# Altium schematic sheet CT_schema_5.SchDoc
size 255 x 245 mm
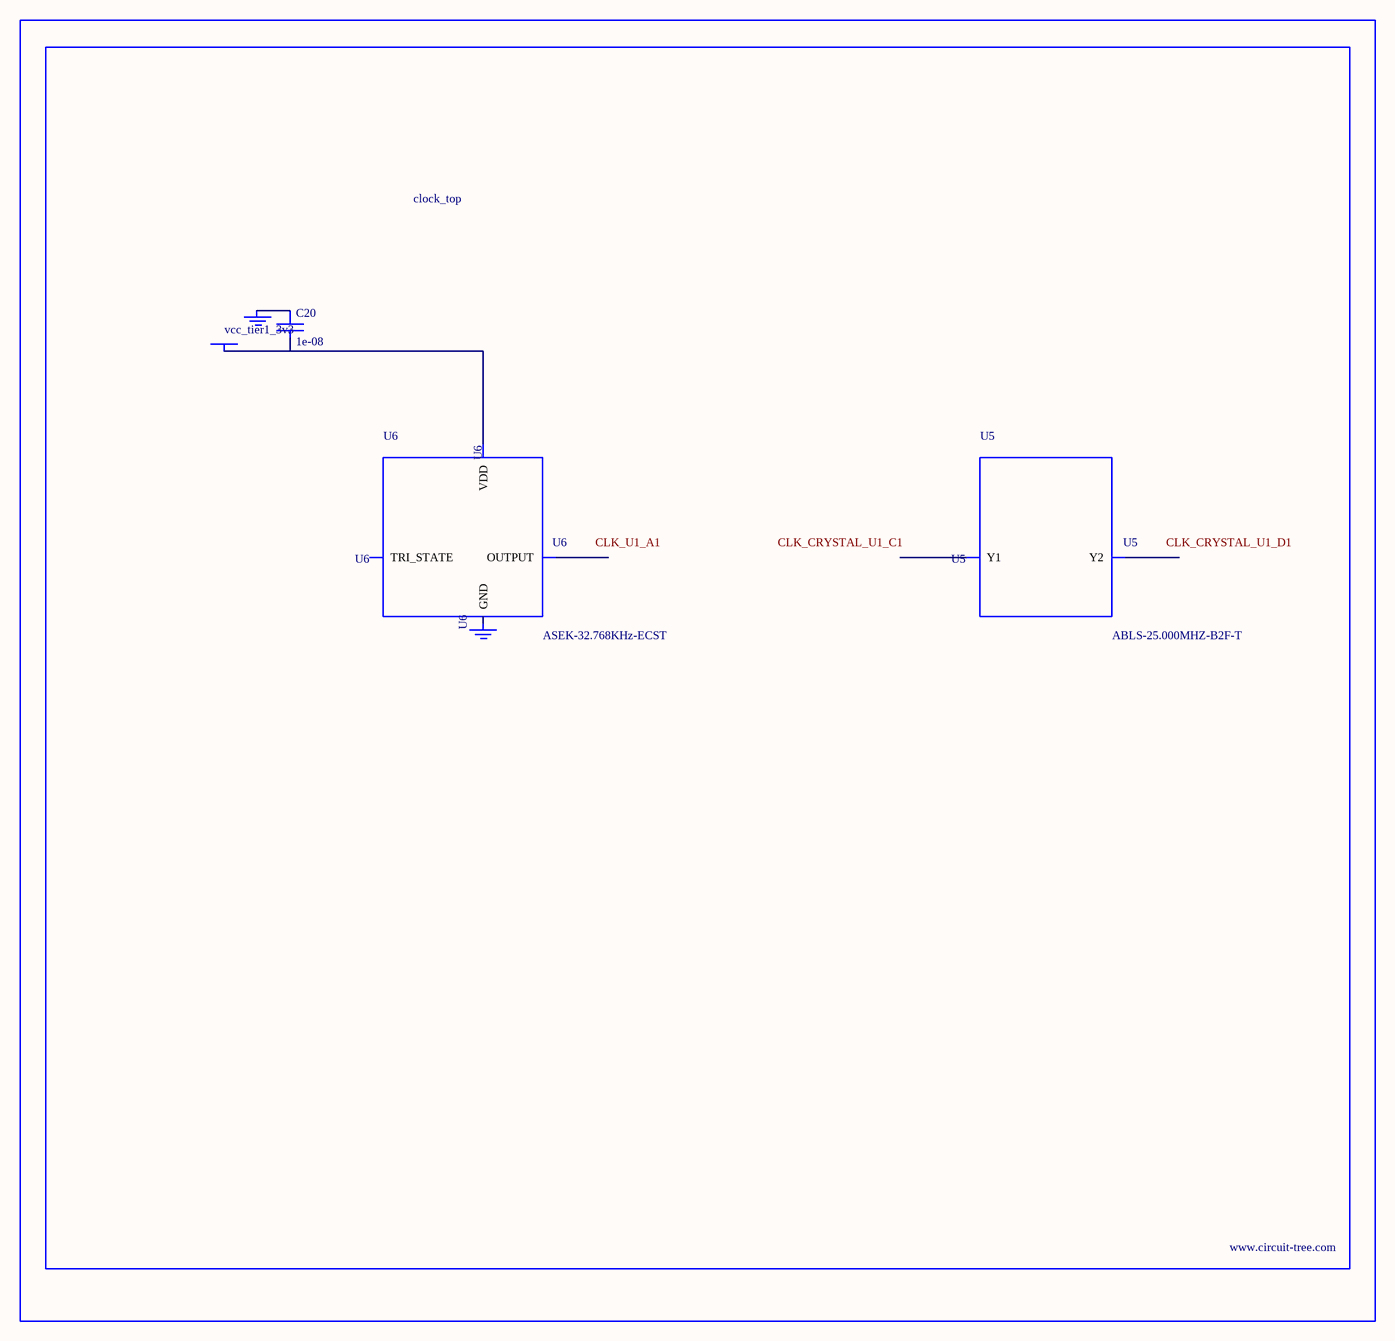
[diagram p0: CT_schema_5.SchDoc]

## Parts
BORDER4  (no value)
C20  1e-08  [C0402]
GND_INSTANCE_4_0  (no value)
GND_INSTANCE_4_1  (no value)
POWER_INSTANCE_4_0  vcc_tier1_3v3
U5  ABLS-25.000MHZ-B2F-T  [ABLS-25.000MHZ-B2F-T]
U6  ASEK-32.768KHz-ECST  [ASEK]

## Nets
NetC20_1: C20.1 GND_INSTANCE_4_0.0(GND)
NetC20_2: C20.2 POWER_INSTANCE_4_0.0(PWR) U6.4(VDD)

Not connected (* = marked no-connect by the designer): GND_INSTANCE_4_1 0(GND); U5 1(Y1) 2(Y2); U6 1(TRI_STATE) 2(GND) 3(OUTPUT)

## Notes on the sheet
- Labels drawn without touching a wire or pin: CLK_CRYSTAL_U1_C1, CLK_CRYSTAL_U1_D1, CLK_U1_A1

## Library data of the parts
BORDER4 = BORDER_PAGE4
C20 = C0402C103K3RAC
GND_INSTANCE_4_0 GND_INSTANCE_4_1 = GND
POWER_INSTANCE_4_0 = PWR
